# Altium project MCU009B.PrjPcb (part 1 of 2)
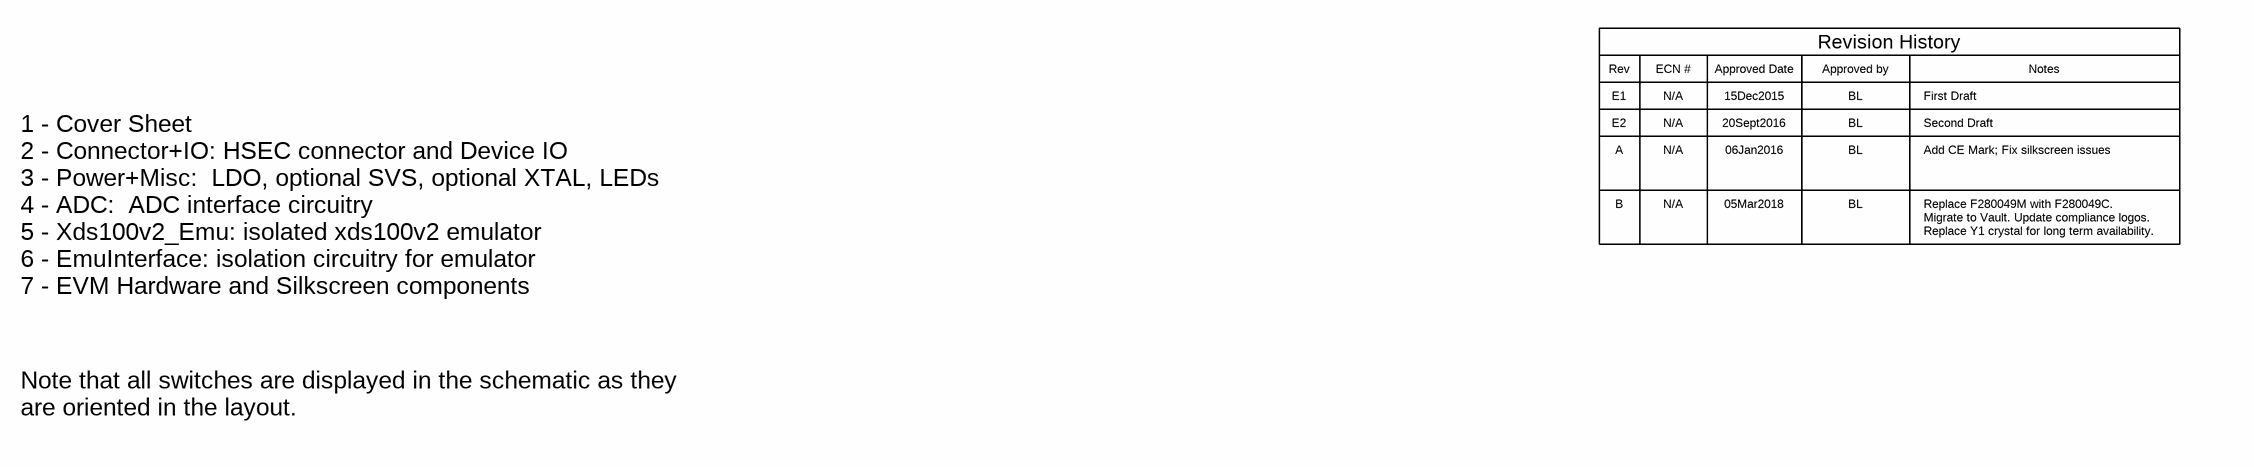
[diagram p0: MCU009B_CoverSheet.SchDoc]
CopyrightYear: 2018; PCB_Layout: QC Graphics; PCB_Rev: B; PRJ_Customer: Public Release; PRJ_Engineer: Brett Larimore; PRJ_Number: MCU009; PRJ_Title: F280049C controlCARD; SCH_Rev: B; TechSupport: http://www.ti.com/support; TID: N/A
7 sheets, 234 parts. Net scope: flat (ports and power ports of the same name join across sheets).
Board file: MCU009B_PCB.PcbDoc
Sheets:
  MCU009B_CoverSheet.SchDoc
  MCU009B_Connector+IO.SchDoc
  MCU009B_Power+Misc.SchDoc
  MCU009B_ADC.SchDoc
  MCU009B_Xds100v2Emu.SchDoc
  MCU009B_EVM_Hardware.SchDoc
  MCU009B_EmuInterface.SchDoc

## Sheet MCU009B_CoverSheet.SchDoc: Cover Sheet
size 431 x 279 mm; Date: Not shown in title block; ApprovedBy: Not shown in title block; CheckedBy: Not shown in title block; Author: Not shown in title block; CompanyName: Not shown in title block; DrawnBy: Brett Larimore; Engineer: Not shown in title block; Organization: Not shown in title block; Address1: Not shown in title block; Address2: Not shown in title block; Address3: Not shown in title block; Address4: Not shown in title block; DocumentNumber: 1; Revision: Use project parameter SCH_Rev; SheetNumber: 1; SheetTotal: 7; PageSetup: Record=PageOptions¦CenterHorizontal=True¦CenterVertical=True¦PrintScale=1.00¦XCorrection=1.00¦YCorrection=1.00¦PrintKind=0¦BorderSize=5000000¦LeftOffset=0¦BottomOffset=0¦Orientation=2¦PaperLength=1000¦PaperWidth=1000¦Scale=100¦PaperSource=15¦PrintQuality=600¦MediaType=1¦DitherType=10¦PaperKind=Letter¦PrintScaleMode=1

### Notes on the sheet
- Rev
- E1
- ECN #
- N/A
- Approved Date
- 15Dec2015
- Approved by
- BL
- Revision History
- First Draft
- Notes
- E2
- A
- 20Sept2016
- 06Jan2016
- Second Draft
- Add CE Mark; Fix silkscreen issues
- B
- 05Mar2018
- Replace F280049M with F280049C.
- Migrate to Vault. Update compliance logos.
- Replace Y1 crystal for long term availability.
- 1 - Cover Sheet
  2 - Connector+IO: HSEC connector and Device IO
  3 - Power+Misc:  LDO, optional SVS, optional XTAL, LEDs
  4 - ADC:  ADC interface circuitry
  5 - Xds100v2_Emu: isolated xds100v2 emulator
  6 - EmuInterface: isolation circuitry for emulator
  7 - EVM Hardware and Silkscreen components
- Note that all switches are displayed in the schematic as they are oriented in the layout.

## Sheet MCU009B_Connector+IO.SchDoc: Connector+IO
size 431 x 279 mm; Date: Not shown in title block; ApprovedBy: Not shown in title block; CheckedBy: Not shown in title block; Author: Not shown in title block; CompanyName: Not shown in title block; Engineer: Not shown in title block; Organization: Not shown in title block; Address1: Not shown in title block; Address2: Not shown in title block; Address3: Not shown in title block; Address4: Not shown in title block; DocumentNumber: 2; Revision: Use project parameter SCH_Rev; SheetNumber: 2; SheetTotal: 7; PageSetup: Record=PageOptions¦CenterHorizontal=True¦CenterVertical=True¦PrintScale=1.00¦XCorrection=1.00¦YCorrection=1.00¦PrintKind=0¦BorderSize=5000000¦LeftOffset=0¦BottomOffset=0¦Orientation=2¦PaperLength=1000¦PaperWidth=1000¦Scale=100¦PaperSource=15¦PrintQuality=600¦MediaType=1¦DitherType=10¦PaperKind=Letter¦PrintScaleMode=1
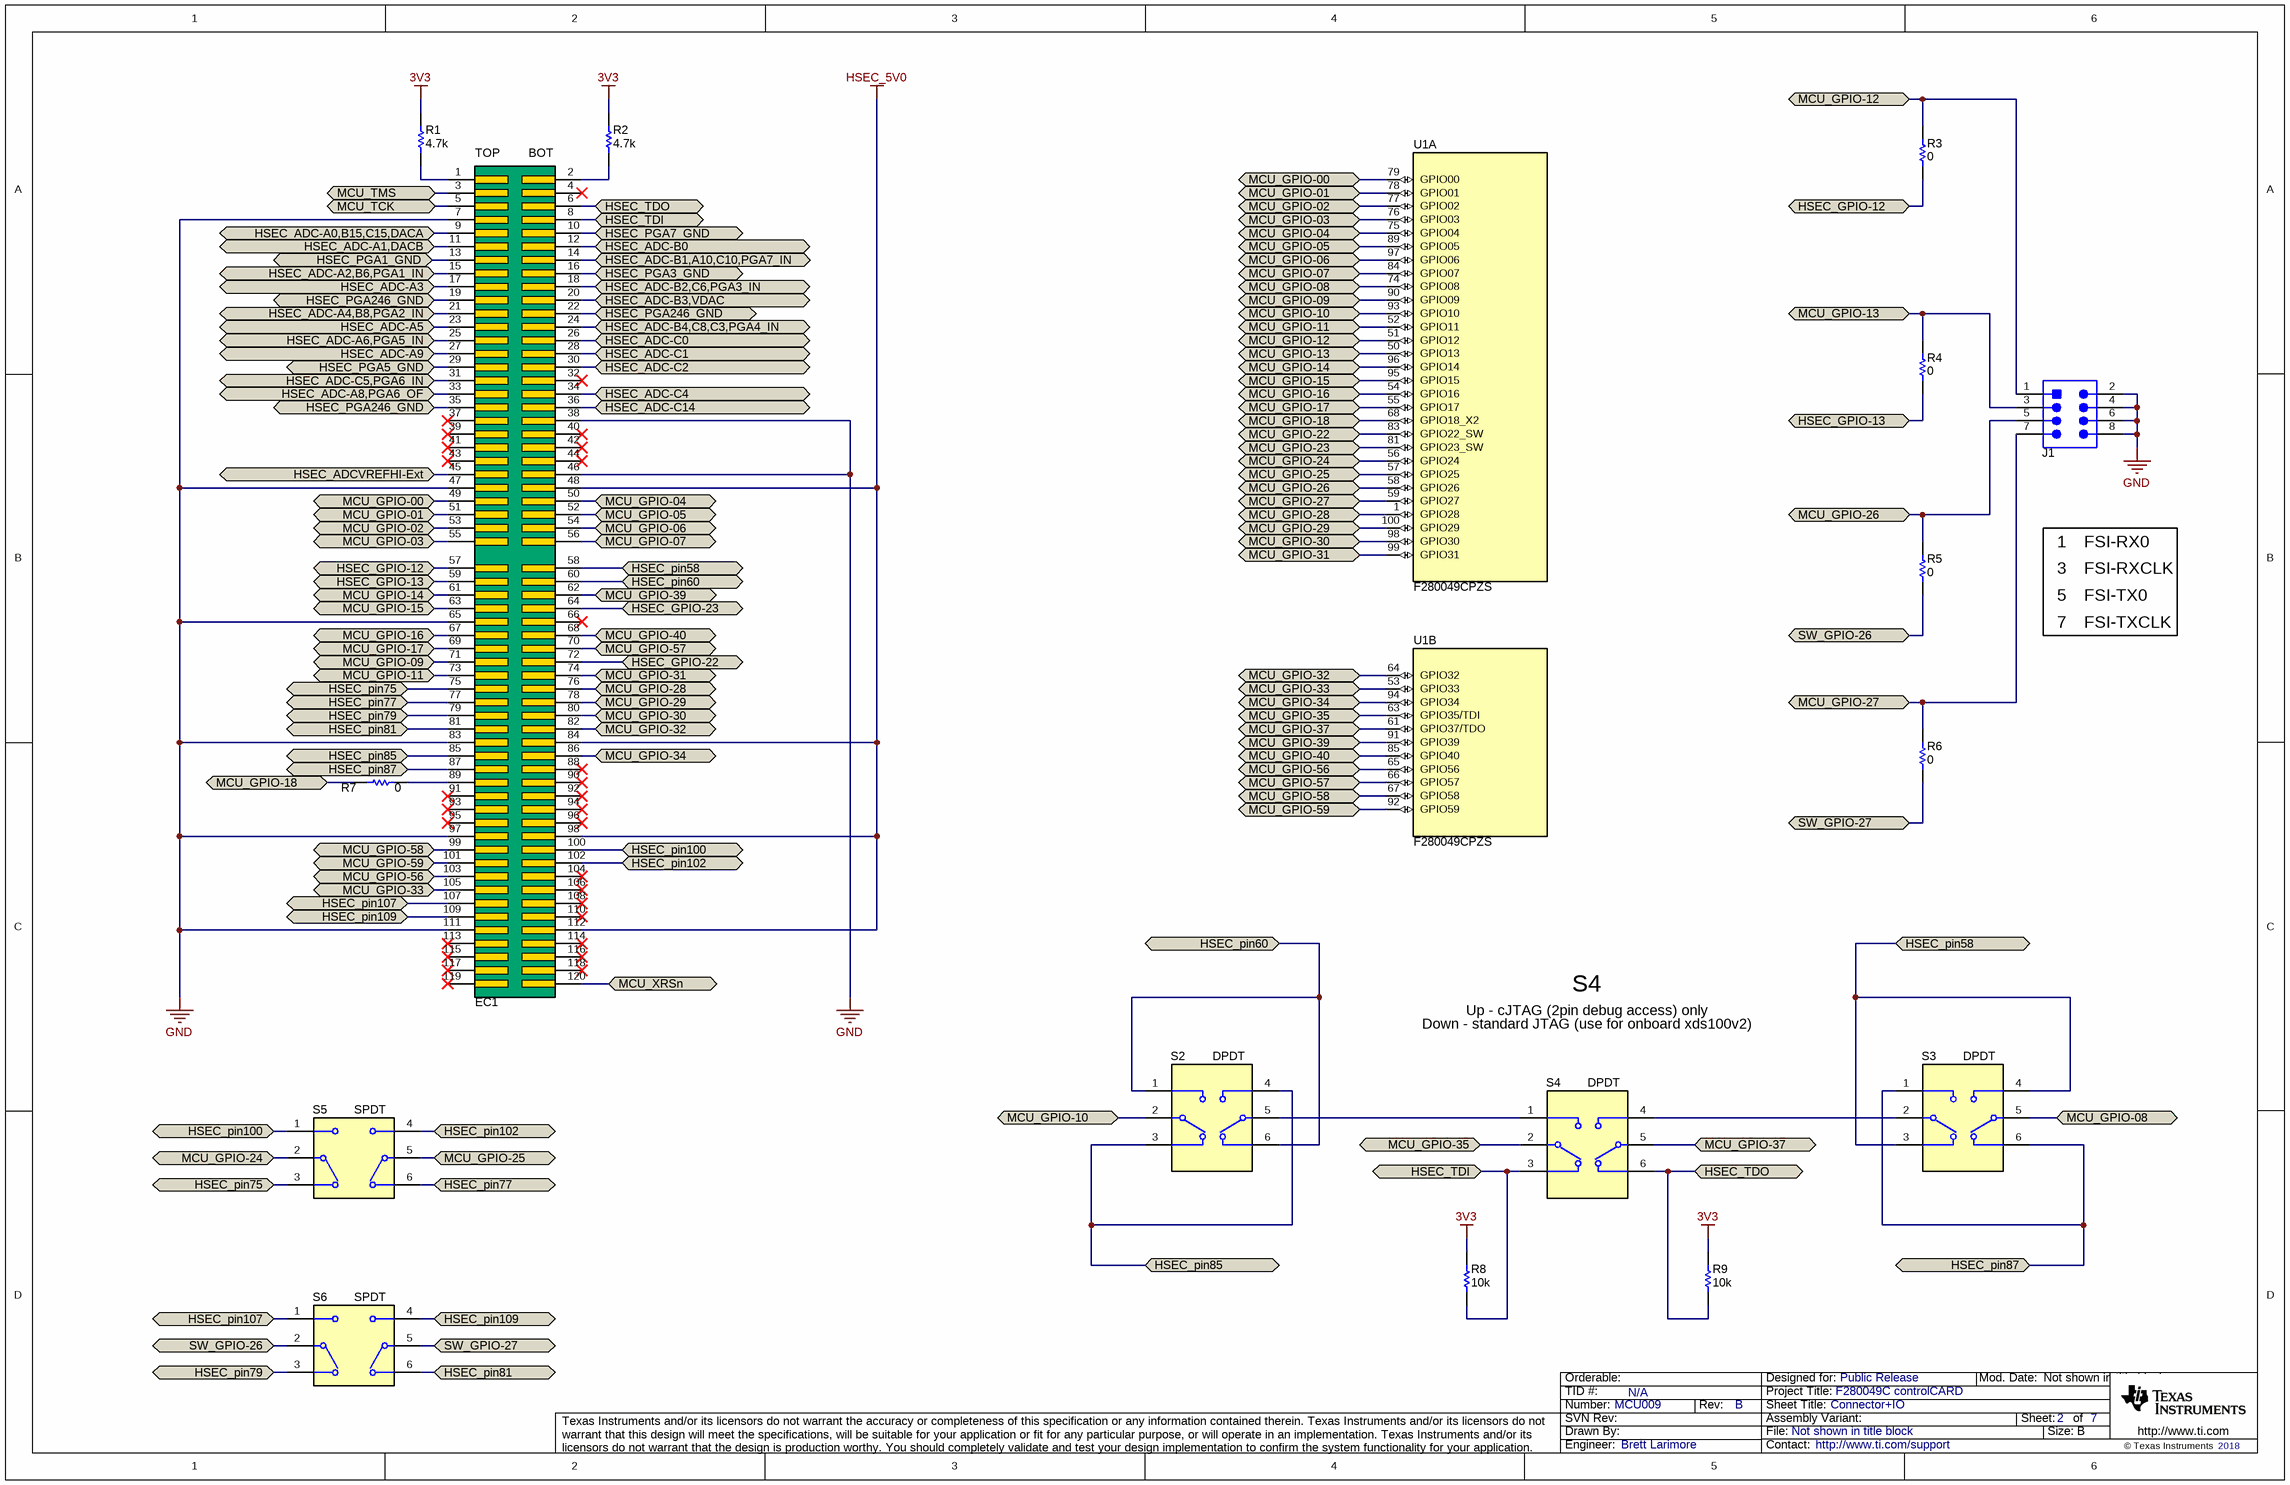
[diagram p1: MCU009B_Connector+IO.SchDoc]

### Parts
(Parts that share a designator on the sheet are numbered #1, #2 ... from top to bottom, then left to right.)
EC1  controlCARD-120HSEC_Edge  [controlCARD-120HSEC_Edge]  (value not drawn)  (no BOM)
J1  TMM-104-01-T-D  [Samtec_TMM-104-01-x-D]  (value not drawn)
R1  ValueDisplayed: 4.7k  [0402]  (hidden comment: CRCW04024K70JNED)
R2  ValueDisplayed: 4.7k  [0402]  (hidden comment: CRCW04024K70JNED)
R3  ValueDisplayed: 0  [0603]  (hidden comment: CRCW06030000Z0EA)
R4  ValueDisplayed: 0  [0603]  (hidden comment: CRCW06030000Z0EA)
R5  ValueDisplayed: 0  [0603]  (hidden comment: CRCW06030000Z0EA)
R6  ValueDisplayed: 0  [0603]  (hidden comment: CRCW06030000Z0EA)
R7  ValueDisplayed: 0  [0603]  (hidden comment: CRCW06030000Z0EA)
R8  ValueDisplayed: 10k  [0402]  (hidden comment: CRCW040210K0JNED)
R9  ValueDisplayed: 10k  [0402]  (hidden comment: CRCW040210K0JNED)
S2  Circuit: DPDT  [SW_CAS-220TA]  (hidden comment: CAS-220TA)
S3  Circuit: DPDT  [SW_CAS-220TA]  (hidden comment: CAS-220TA)
S4  Circuit: DPDT  [SW_CAS-220TA]  (hidden comment: CAS-220TA)
S5  Circuit: SPDT  [SW_CAS-D20TA]  (hidden comment: CAS-D20TA)
S6  Circuit: SPDT  [SW_CAS-D20TA]  (hidden comment: CAS-D20TA)
U1#1  F280049CPZS  [PZ0100A_N]  (parts A,B of 5)

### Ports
HSEC_ADC-A0,B15,C15,DACA (bidir), HSEC_ADC-A1,DACB (bidir), HSEC_ADC-A2,B6,PGA1_IN (bidir), HSEC_ADC-A3 (bidir), HSEC_ADC-A4,B8,PGA2_IN (bidir), HSEC_ADC-A5 (bidir), HSEC_ADC-A6,PGA5_IN (bidir), HSEC_ADC-A8,PGA6_OF (bidir), HSEC_ADC-A9 (bidir), HSEC_ADC-B0 (bidir), HSEC_ADC-B1,A10,C10,PGA7_IN (bidir), HSEC_ADC-B2,C6,PGA3_IN (bidir), HSEC_ADC-B3,VDAC (bidir), HSEC_ADC-B4,C8,C3,PGA4_IN (bidir), HSEC_ADC-C0 (bidir), HSEC_ADC-C1 (bidir), HSEC_ADC-C2 (bidir), HSEC_ADC-C4 (bidir), HSEC_ADC-C5,PGA6_IN (bidir), HSEC_ADC-C14 (bidir), HSEC_ADCVREFHI-Ext (bidir), HSEC_GPIO-12 (bidir), HSEC_GPIO-13 (bidir), HSEC_GPIO-22 (bidir), HSEC_GPIO-23 (bidir), HSEC_PGA1_GND (bidir), HSEC_PGA3_GND (bidir), HSEC_PGA5_GND (bidir), HSEC_PGA7_GND (bidir), HSEC_PGA246_GND (bidir), HSEC_pin58 (bidir), HSEC_pin60 (bidir), HSEC_pin75 (bidir), HSEC_pin77 (bidir), HSEC_pin79 (bidir), HSEC_pin81 (bidir), HSEC_pin85 (bidir), HSEC_pin87 (bidir), HSEC_pin100 (bidir), HSEC_pin102 (bidir), HSEC_pin107 (bidir), HSEC_pin109 (bidir), HSEC_TDI (bidir), HSEC_TDO (bidir), MCU_GPIO-00 (bidir), MCU_GPIO-01 (bidir), MCU_GPIO-02 (bidir), MCU_GPIO-03 (bidir), MCU_GPIO-04 (bidir), MCU_GPIO-05 (bidir), MCU_GPIO-06 (bidir), MCU_GPIO-07 (bidir), MCU_GPIO-08 (bidir), MCU_GPIO-09 (bidir), MCU_GPIO-10 (bidir), MCU_GPIO-11 (bidir), MCU_GPIO-12 (bidir), MCU_GPIO-13 (bidir), MCU_GPIO-14 (bidir), MCU_GPIO-15 (bidir), MCU_GPIO-16 (bidir), MCU_GPIO-17 (bidir), MCU_GPIO-18 (bidir), MCU_GPIO-22 (bidir), MCU_GPIO-23 (bidir), MCU_GPIO-24 (bidir), MCU_GPIO-25 (bidir), MCU_GPIO-26 (bidir), MCU_GPIO-27 (bidir), MCU_GPIO-28 (bidir), MCU_GPIO-29 (bidir), MCU_GPIO-30 (bidir), MCU_GPIO-31 (bidir), MCU_GPIO-32 (bidir), MCU_GPIO-33 (bidir), MCU_GPIO-34 (bidir), MCU_GPIO-35 (bidir), MCU_GPIO-37 (bidir), MCU_GPIO-39 (bidir), MCU_GPIO-40 (bidir), MCU_GPIO-56 (bidir), MCU_GPIO-57 (bidir), MCU_GPIO-58 (bidir), MCU_GPIO-59 (bidir), MCU_TCK (bidir), MCU_TMS (bidir), MCU_XRSn (bidir), SW_GPIO-26 (bidir), SW_GPIO-27 (bidir)

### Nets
3V3: R1.1 R2.2 R8.2 R9.2
GND: EC1.7 EC1.38 EC1.46 EC1.47 EC1.65 EC1.83 EC1.97 EC1.111 J1.2 J1.4 J1.6 J1.8
HSEC_5V0: EC1.48 EC1.84 EC1.98 EC1.112
HSEC_ADC-A0,B15,C15,DACA: EC1.9 ; port HSEC_ADC-A0,B15,C15,DACA
HSEC_ADC-A1,DACB: EC1.11 ; port HSEC_ADC-A1,DACB
HSEC_ADC-A2,B6,PGA1_IN: EC1.15 ; port HSEC_ADC-A2,B6,PGA1_IN
HSEC_ADC-A3: EC1.17 ; port HSEC_ADC-A3
HSEC_ADC-A4,B8,PGA2_IN: EC1.21 ; port HSEC_ADC-A4,B8,PGA2_IN
HSEC_ADC-A5: EC1.23 ; port HSEC_ADC-A5
HSEC_ADC-A6,PGA5_IN: EC1.25 ; port HSEC_ADC-A6,PGA5_IN
HSEC_ADC-A8,PGA6_OF: EC1.33 ; port HSEC_ADC-A8,PGA6_OF
HSEC_ADC-A9: EC1.27 ; port HSEC_ADC-A9
HSEC_ADC-B0: EC1.12 ; port HSEC_ADC-B0
HSEC_ADC-B1,A10,C10,PGA7_IN: EC1.14 ; port HSEC_ADC-B1,A10,C10,PGA7_IN
HSEC_ADC-B2,C6,PGA3_IN: EC1.18 ; port HSEC_ADC-B2,C6,PGA3_IN
HSEC_ADC-B3,VDAC: EC1.20 ; port HSEC_ADC-B3,VDAC
HSEC_ADC-B4,C8,C3,PGA4_IN: EC1.24 ; port HSEC_ADC-B4,C8,C3,PGA4_IN
HSEC_ADC-C0: EC1.26 ; port HSEC_ADC-C0
HSEC_ADC-C1: EC1.28 ; port HSEC_ADC-C1
HSEC_ADC-C2: EC1.30 ; port HSEC_ADC-C2
HSEC_ADC-C4: EC1.34 ; port HSEC_ADC-C4
HSEC_ADC-C5,PGA6_IN: EC1.31 ; port HSEC_ADC-C5,PGA6_IN
HSEC_ADC-C14: EC1.36 ; port HSEC_ADC-C14
HSEC_ADCVREFHI-Ext: EC1.45 ; port HSEC_ADCVREFHI-Ext
HSEC_GPIO-12: EC1.57 R3.1 ; port HSEC_GPIO-12
HSEC_GPIO-13: EC1.59 R4.1 ; port HSEC_GPIO-13
HSEC_GPIO-22: EC1.72 ; port HSEC_GPIO-22
HSEC_GPIO-23: EC1.64 ; port HSEC_GPIO-23
HSEC_PGA1_GND: EC1.13 ; port HSEC_PGA1_GND
HSEC_PGA3_GND: EC1.16 ; port HSEC_PGA3_GND
HSEC_PGA5_GND: EC1.29 ; port HSEC_PGA5_GND
HSEC_PGA7_GND: EC1.10 ; port HSEC_PGA7_GND
HSEC_PGA246_GND: EC1.19 EC1.22 EC1.35 ; port HSEC_PGA246_GND
HSEC_pin58: EC1.58 S3.3 S3.4 ; port HSEC_pin58
HSEC_pin60: EC1.60 S2.1 S2.6 ; port HSEC_pin60
HSEC_pin75: EC1.75 S5.3 ; port HSEC_pin75
HSEC_pin77: EC1.77 S5.6 ; port HSEC_pin77
HSEC_pin79: EC1.79 S6.3 ; port HSEC_pin79
HSEC_pin81: EC1.81 S6.6 ; port HSEC_pin81
HSEC_pin85: EC1.85 S2.3 S2.4 ; port HSEC_pin85
HSEC_pin87: EC1.87 S3.1 S3.6 ; port HSEC_pin87
HSEC_pin100: EC1.100 S5.1 ; port HSEC_pin100
HSEC_pin102: EC1.102 S5.4 ; port HSEC_pin102
HSEC_pin107: EC1.107 S6.1 ; port HSEC_pin107
HSEC_pin109: EC1.109 S6.4 ; port HSEC_pin109
HSEC_TDI: EC1.8 R8.1 S4.3 ; port HSEC_TDI
HSEC_TDO: EC1.6 R9.1 S4.6 ; port HSEC_TDO
MCU_GPIO-00: EC1.49 U1#1.79(GPIO00) ; port MCU_GPIO-00
MCU_GPIO-01: EC1.51 U1#1.78(GPIO01) ; port MCU_GPIO-01
MCU_GPIO-02: EC1.53 U1#1.77(GPIO02) ; port MCU_GPIO-02
MCU_GPIO-03: EC1.55 U1#1.76(GPIO03) ; port MCU_GPIO-03
MCU_GPIO-04: EC1.50 U1#1.75(GPIO04) ; port MCU_GPIO-04
MCU_GPIO-05: EC1.52 U1#1.89(GPIO05) ; port MCU_GPIO-05
MCU_GPIO-06: EC1.54 U1#1.97(GPIO06) ; port MCU_GPIO-06
MCU_GPIO-07: EC1.56 U1#1.84(GPIO07) ; port MCU_GPIO-07
MCU_GPIO-08: S3.5 U1#1.74(GPIO08) ; port MCU_GPIO-08
MCU_GPIO-09: EC1.71 U1#1.90(GPIO09) ; port MCU_GPIO-09
MCU_GPIO-10: S2.2 U1#1.93(GPIO10) ; port MCU_GPIO-10
MCU_GPIO-11: EC1.73 U1#1.52(GPIO11) ; port MCU_GPIO-11
MCU_GPIO-12: J1.1 R3.2 U1#1.51(GPIO12) ; port MCU_GPIO-12
MCU_GPIO-13: J1.3 R4.2 U1#1.50(GPIO13) ; port MCU_GPIO-13
MCU_GPIO-14: EC1.61 U1#1.96(GPIO14) ; port MCU_GPIO-14
MCU_GPIO-15: EC1.63 U1#1.95(GPIO15) ; port MCU_GPIO-15
MCU_GPIO-16: EC1.67 U1#1.54(GPIO16) ; port MCU_GPIO-16
MCU_GPIO-17: EC1.69 U1#1.55(GPIO17) ; port MCU_GPIO-17
MCU_GPIO-18: R7.2 U1#1.68(GPIO18_X2) ; port MCU_GPIO-18
MCU_GPIO-22: U1#1.83(GPIO22_SW) ; port MCU_GPIO-22
MCU_GPIO-23: U1#1.81(GPIO23_SW) ; port MCU_GPIO-23
MCU_GPIO-24: S5.2(C) U1#1.56(GPIO24) ; port MCU_GPIO-24
MCU_GPIO-25: S5.5(C) U1#1.57(GPIO25) ; port MCU_GPIO-25
MCU_GPIO-26: J1.5 R5.2 U1#1.58(GPIO26) ; port MCU_GPIO-26
MCU_GPIO-27: J1.7 R6.2 U1#1.59(GPIO27) ; port MCU_GPIO-27
MCU_GPIO-28: EC1.76 U1#1.1(GPIO28) ; port MCU_GPIO-28
MCU_GPIO-29: EC1.78 U1#1.100(GPIO29) ; port MCU_GPIO-29
MCU_GPIO-30: EC1.80 U1#1.98(GPIO30) ; port MCU_GPIO-30
MCU_GPIO-31: EC1.74 U1#1.99(GPIO31) ; port MCU_GPIO-31
MCU_GPIO-32: EC1.82 U1#1.64(GPIO32) ; port MCU_GPIO-32
MCU_GPIO-33: EC1.105 U1#1.53(GPIO33) ; port MCU_GPIO-33
MCU_GPIO-34: EC1.86 U1#1.94(GPIO34) ; port MCU_GPIO-34
MCU_GPIO-35: S4.2 U1#1.63(GPIO35/TDI) ; port MCU_GPIO-35
MCU_GPIO-37: S4.5 U1#1.61(GPIO37/TDO) ; port MCU_GPIO-37
MCU_GPIO-39: EC1.62 U1#1.91(GPIO39) ; port MCU_GPIO-39
MCU_GPIO-40: EC1.68 U1#1.85(GPIO40) ; port MCU_GPIO-40
MCU_GPIO-56: EC1.103 U1#1.65(GPIO56) ; port MCU_GPIO-56
MCU_GPIO-57: EC1.70 U1#1.66(GPIO57) ; port MCU_GPIO-57
MCU_GPIO-58: EC1.99 U1#1.67(GPIO58) ; port MCU_GPIO-58
MCU_GPIO-59: EC1.101 U1#1.92(GPIO59) ; port MCU_GPIO-59
MCU_TCK: EC1.5 ; port MCU_TCK
MCU_TMS: EC1.3 ; port MCU_TMS
MCU_XRSn: EC1.120 ; port MCU_XRSn
SW_GPIO-26: R5.1 S6.2(C) ; port SW_GPIO-26
SW_GPIO-27: R6.1 S6.5(C) ; port SW_GPIO-27
NetEC1_1: EC1.1 R1.2
NetEC1_2: EC1.2 R2.1
NetEC1_89: EC1.89 R7.1
NetS2_5: S2.5 S4.1
NetS3_2: S3.2 S4.4

Not connected (* = marked no-connect by the designer): EC1 4* 32* 37* 39* 40* 41* 42* 43* 44* 66* 88* 90* 91* 92* 93* 94* 95* 96* 104* 106* 108* 110* 113* 114* 115* 116* 117* 118* 119*

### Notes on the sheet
- 1
- 3
- FSI-RX0
- FSI-RXCLK
- 5
- 7
- FSI-TX0
- FSI-TXCLK
- S4
- Up - cJTAG (2pin debug access) only
- Down - standard JTAG (use for onboard xds100v2)

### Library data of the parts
EC1 = CMP-0003813-2: C2000 controlCARD-120HSEC Edge Connector for Samtec HSEC8-160-01-L-DV-A-BL; Manufacturer: Any; Note: The pin numbering does not match Samtec datasheet
J1 = CMP-0055568-1: Header, 2mm, 4x2, Tin, TH; Manufacturer: Samtec; Pitch_mm: 2; Gender: Male; Shrouded: N; Current_A: 3.2A; Cert_CSA: Y; CNHeader: TRUE; CT: FALSE
R1 R2 = CMP-0026938-5: RES, 4.7 k, 5%, 0.063 W, AEC-Q200 Grade 0, 0402; Manufacturer: Vishay-Dale; Value: 4.7k; Value_Code: 4k70; Power_W: 63mW; Value2: 0.063W; VDC_V: 50V; TempCo: 200 ppm/C; EIA_Code: E24; AEC Category: Q200; AEC Qualified: Y; AEC Grade: 0; SizeArea_mm2: 0.5; SizeX_mm: 1; SizeZ_mm: 0.6
R3-R7 = CMP-0025697-4: RES, 0, 5%, 0.1 W, AEC-Q200 Grade 0, 0603; Manufacturer: Vishay-Dale; Value: 0; Value_Code: 0000; Power_W: 100mW; Value2: 0.1W; VDC_V: 75V; TempCo: 200 ppm/C; EIA_Code: E24; AEC Category: Q200; AEC Qualified: Y; SizeArea_mm2: 1.28; SizeX_mm: 1.6; SizeY_mm: 0.8; SizeZ_mm: 1
R8 R9 = CMP-0026825-5: RES, 10 k, 5%, 0.063 W, AEC-Q200 Grade 0, 0402; Manufacturer: Vishay-Dale; Value: 10k; Value_Code: 10k0; Power_W: 63mW; Value2: 0.063W; VDC_V: 50V; TempCo: 200 ppm/C; EIA_Code: E24; AEC Category: Q200; AEC Qualified: Y; AEC Grade: 0; SizeArea_mm2: 0.5; SizeX_mm: 1; SizeZ_mm: 0.6
S2-S4 = CMP-0002123-2: SLIDE SWITCH DPDT  .1A, SMT; Manufacturer: Copal Electronics; VDC_V: 6V; SwitchFunction: On-On; PositionCount: 2; CurrentRating_mA: 100A
S5 S6 = CMP-0002233-1: Switch, Dual SPDT,  2 Pos, 0.1A, 6VDC, SMD; Manufacturer: Copal Electronics; VDC_V: 6V; SwitchFunction: On-On; PositionCount: 2; CurrentRating_mA: 100A
U1#1 = CMP-0078352-1: Piccolo Microcontroller, PZ0100A (LQFP-100); Manufacturer: Texas Instruments; SizeArea_mm2: 256; SizeAreaWB_mm2: 324; SizeX_mm: 16; SizeZ_mm: 1.6; CompType: IC; AEC Category: Q200; AEC Qualified: N

## Sheet MCU009B_Power+Misc.SchDoc: Power+Misc
size 431 x 279 mm; Date: Not shown in title block; ApprovedBy: Not shown in title block; CheckedBy: Not shown in title block; Author: Not shown in title block; CompanyName: Not shown in title block; Engineer: Not shown in title block; Organization: Not shown in title block; Address1: Not shown in title block; Address2: Not shown in title block; Address3: Not shown in title block; Address4: Not shown in title block; DocumentNumber: 3; Revision: Use project parameter SCH_Rev; SheetNumber: 3; SheetTotal: 7; PageSetup: Record=PageOptions¦CenterHorizontal=True¦CenterVertical=True¦PrintScale=0.64¦XCorrection=1.00¦YCorrection=1.00¦PrintKind=0¦BorderSize=5000000¦LeftOffset=0¦BottomOffset=0¦Orientation=2¦PaperLength=1000¦PaperWidth=1000¦Scale=100¦PaperSource=15¦PrintQuality=600¦MediaType=1¦DitherType=10¦PrintScaleMode=1¦PaperKind=Letter
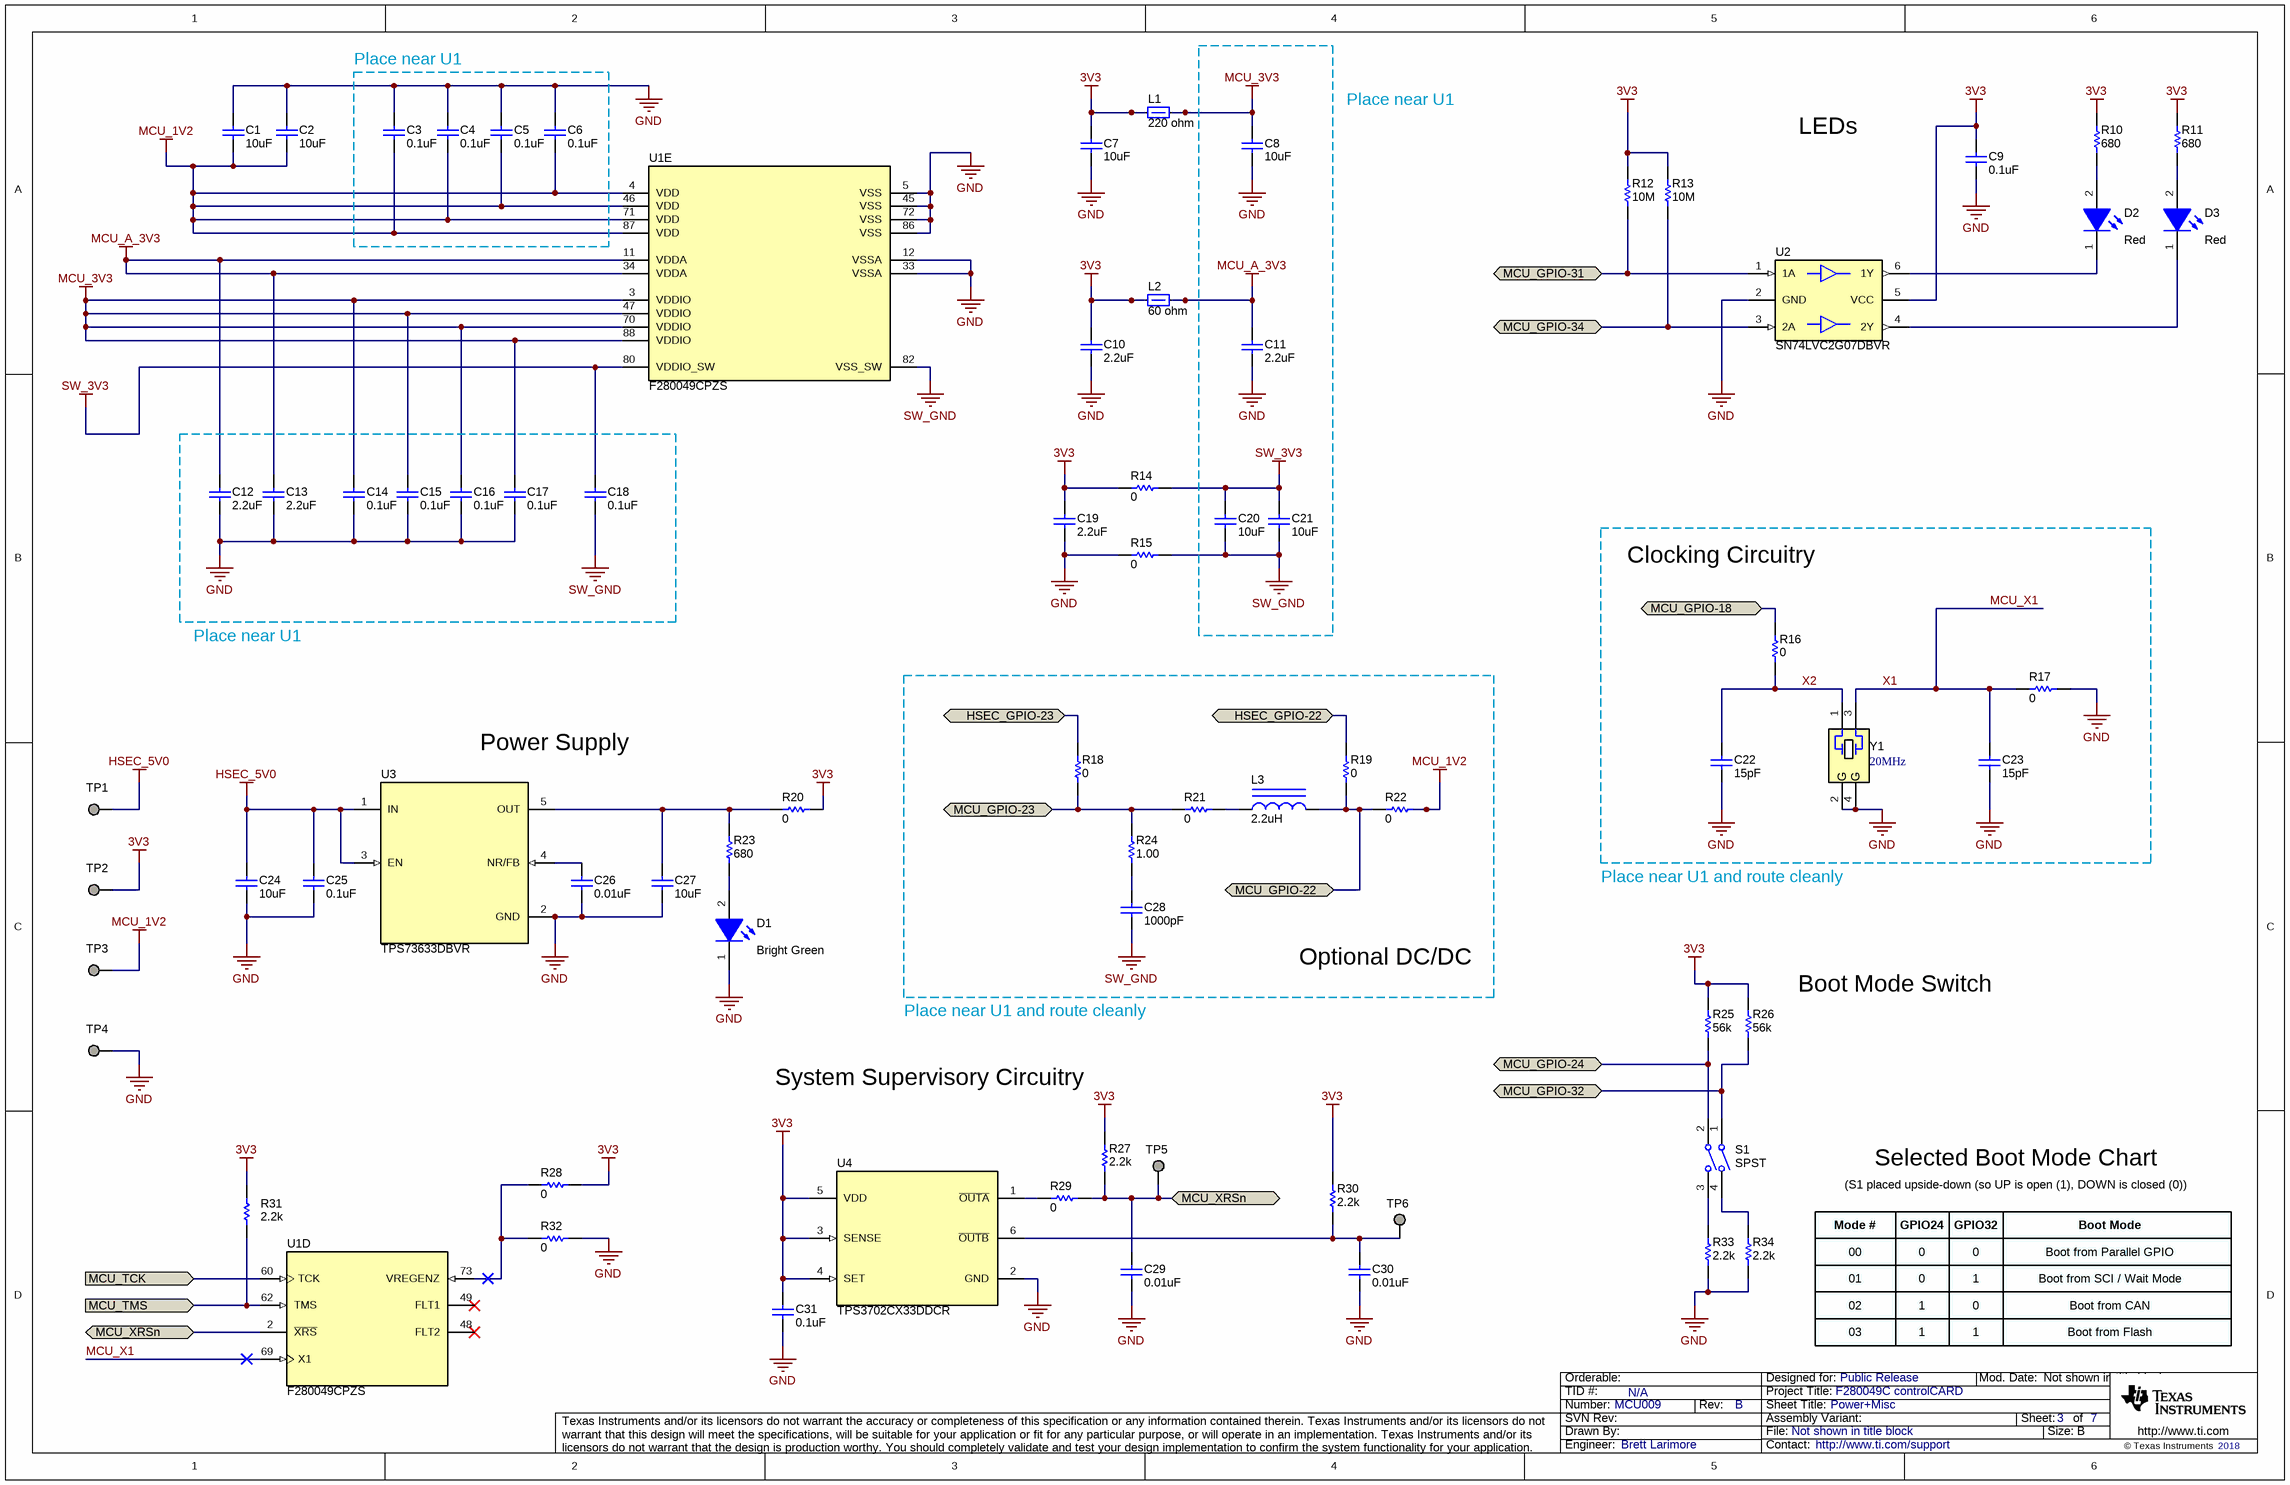
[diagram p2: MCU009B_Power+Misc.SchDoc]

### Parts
(Parts that share a designator on the sheet are numbered #1, #2 ... from top to bottom, then left to right.)
C1  ValueDisplayed: 10uF  [0603]  (hidden comment: GRM188R61A106ME69D)
C2  ValueDisplayed: 10uF  [0603]  (hidden comment: GRM188R61A106ME69D)
C3  ValueDisplayed: 0.1uF  [0402]  (hidden comment: GRM155R71A104KA01D)
C4  ValueDisplayed: 0.1uF  [0402]  (hidden comment: GRM155R71A104KA01D)
C5  ValueDisplayed: 0.1uF  [0402]  (hidden comment: GRM155R71A104KA01D)
C6  ValueDisplayed: 0.1uF  [0402]  (hidden comment: GRM155R71A104KA01D)
C7  ValueDisplayed: 10uF  [0805_HV]  (hidden comment: GRM21BR61A106KE19L)
C8  ValueDisplayed: 10uF  [0603]  (hidden comment: GRM188R61A106ME69D)
C9  ValueDisplayed: 0.1uF  [0402]  (hidden comment: GRM155R71A104KA01D)
C10  ValueDisplayed: 2.2uF  [0603]  (hidden comment: GRM188R61A225KE34D)
C11  ValueDisplayed: 2.2uF  [0603]  (hidden comment: GRM188R61A225KE34D)
C12  ValueDisplayed: 2.2uF  [0603]  (hidden comment: GRM188R61A225KE34D)
C13  ValueDisplayed: 2.2uF  [0603]  (hidden comment: GRM188R61A225KE34D)
C14  ValueDisplayed: 0.1uF  [0402]  (hidden comment: GRM155R71A104KA01D)
C15  ValueDisplayed: 0.1uF  [0402]  (hidden comment: GRM155R71A104KA01D)
C16  ValueDisplayed: 0.1uF  [0402]  (hidden comment: GRM155R71A104KA01D)
C17  ValueDisplayed: 0.1uF  [0402]  (hidden comment: GRM155R71A104KA01D)
C18  ValueDisplayed: 0.1uF  [0402]  (hidden comment: GRM155R71A104KA01D)
C19  ValueDisplayed: 2.2uF  [0603]  (hidden comment: GRM188R61A225KE34D)
C20  ValueDisplayed: 10uF  [0603]  (hidden comment: GRM188R61A106ME69D)
C21  ValueDisplayed: 10uF  [0603]  (hidden comment: GRM188R61A106ME69D)
C22  ValueDisplayed: 15pF  [0402]  (hidden comment: GRM1555C1H150JA01D)
C23  ValueDisplayed: 15pF  [0402]  (hidden comment: GRM1555C1H150JA01D)
C24  ValueDisplayed: 10uF  [0603]  (hidden comment: GRM188R61A106ME69D)
C25  ValueDisplayed: 0.1uF  [0402]  (hidden comment: GRM155R71A104KA01D)
C26  ValueDisplayed: 0.01uF  [0402]  (hidden comment: GRM155R71C103KA01D)
C27  ValueDisplayed: 10uF  [0603]  (hidden comment: GRM188R61A106ME69D)
C28  ValueDisplayed: 1000pF  [0402]  (hidden comment: GRM155R71C102KA01D)
C29  ValueDisplayed: 0.01uF  [0402]  (hidden comment: GRM155R71C103KA01D)
C30  ValueDisplayed: 0.01uF  [0402]  (hidden comment: GRM155R71C103KA01D)
C31  ValueDisplayed: 0.1uF  [0402]  (hidden comment: GRM155R71A104KA01D)
D1  value Bright Green  [WL-SMCW_Green_0805]  (hidden comment: 150080VS75000)
D2  value Red  [WL-SMCW_RED_0805]  (hidden comment: 150080SS75000)
D3  value Red  [WL-SMCW_RED_0805]  (hidden comment: 150080SS75000)
L1  value 220 ohm  [0805_HV]  (hidden comment: BLM21PG221SN1D)
L2  value 60 ohm  [0805_HV]  (hidden comment: BKP2125HS600-T)
L3  ValueDisplayed: 2.2uH  [1008]  (hidden comment: LQM2HPN2R2MG0L)
R10  ValueDisplayed: 680  [0402]  (hidden comment: CRCW0402680RJNED)
R11  ValueDisplayed: 680  [0402]  (hidden comment: CRCW0402680RJNED)
R12  ValueDisplayed: 10M  [0402]  (hidden comment: CRCW040210M0JNED)
R13  ValueDisplayed: 10M  [0402]  (hidden comment: CRCW040210M0JNED)
R14  ValueDisplayed: 0  [0805_HV]  (hidden comment: CRCW08050000Z0EA)
R15  ValueDisplayed: 0  [0805_HV]  (hidden comment: CRCW08050000Z0EA)
R16  ValueDisplayed: 0  [0603]  (hidden comment: CRCW06030000Z0EA)
R17  ValueDisplayed: 0  [0603]  (hidden comment: CRCW06030000Z0EA)
R18  ValueDisplayed: 0  [0603]  (hidden comment: CRCW06030000Z0EA)
R19  ValueDisplayed: 0  [0603]  (hidden comment: CRCW06030000Z0EA)
R20  ValueDisplayed: 0  [0805_HV]  (hidden comment: CRCW08050000Z0EA)
R21  ValueDisplayed: 0  [0603]  (hidden comment: CRCW06030000Z0EA)
R22  ValueDisplayed: 0  [0603]  (hidden comment: CRCW06030000Z0EA)
R23  ValueDisplayed: 680  [0402]  (hidden comment: CRCW0402680RJNED)
R24  ValueDisplayed: 1.00  [0402]  (hidden comment: CRCW04021R00FKED)
R25  ValueDisplayed: 56k  [0402]  (hidden comment: CRCW040256K0JNED)
R26  ValueDisplayed: 56k  [0402]  (hidden comment: CRCW040256K0JNED)
R27  ValueDisplayed: 2.2k  [0402]  (hidden comment: CRCW04022K20JNED)
R28  ValueDisplayed: 0  [0603]  (hidden comment: CRCW06030000Z0EA)
R29  ValueDisplayed: 0  [0402]  (hidden comment: CRCW04020000Z0ED)
R30  ValueDisplayed: 2.2k  [0402]  (hidden comment: CRCW04022K20JNED)
R31  ValueDisplayed: 2.2k  [0402]  (hidden comment: CRCW04022K20JNED)
R32  ValueDisplayed: 0  [0603]  (hidden comment: CRCW06030000Z0EA)
R33  ValueDisplayed: 2.2k  [0402]  (hidden comment: CRCW04022K20JNED)
R34  ValueDisplayed: 2.2k  [0402]  (hidden comment: CRCW04022K20JNED)
S1  Circuit: SPST  [SW_218-2LP]  (hidden comment: 218-2LPST)
TP1  TESTPOINT  [TP_50MIL-25MILHOLE]  (value not drawn)  (no BOM)
TP2  TESTPOINT  [TP_50MIL-25MILHOLE]  (value not drawn)  (no BOM)
TP3  TESTPOINT  [TP_50MIL-25MILHOLE]  (value not drawn)  (no BOM)
TP4  TESTPOINT  [TP_50MIL-25MILHOLE]  (value not drawn)  (no BOM)
TP5  TESTPOINT  [TP_50MIL-25MILHOLE]  (value not drawn)  (no BOM)
TP6  TESTPOINT  [TP_50MIL-25MILHOLE]  (value not drawn)  (no BOM)
U1#1  F280049CPZS  [PZ0100A_N]  (parts D,E of 5)
U2  SN74LVC2G07DBVR  [DBV0006A_N]
U3  TPS73633DBVR  [DBV0005A_N]
U4  TPS3702CX33DDCR  [DDC0006A_N]
Y1  20MHz  [ECS_ECX-53B]

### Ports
HSEC_GPIO-22 (bidir), HSEC_GPIO-23 (bidir), MCU_GPIO-18 (bidir), MCU_GPIO-22 (bidir), MCU_GPIO-23 (bidir), MCU_GPIO-24 (bidir), MCU_GPIO-31 (bidir), MCU_GPIO-32 (bidir), MCU_GPIO-34 (bidir), MCU_TCK (in), MCU_TMS (in), MCU_XRSn (bidir)

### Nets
3V3: C7.2 C9.1 C10.2 C19.2 C31.1 L1.1 L2.1 R10.1 R11.1 R12.2 R13.2 R14.1 R20.2 R25.1 R26.2 R27.2 R28.2 R30.2 R31.2 TP2.1 U2.5(VCC) U4.3(SENSE) U4.4(SET) U4.5(VDD)
GND: C1.2 C2.2 C3.1 C4.1 C5.1 C6.1 C7.1 C8.2 C9.2 C10.1 C11.1 C12.1 C13.1 C14.2 C15.2 C16.2 C17.2 C19.1 C22.2 C23.2 C24.2 C25.2 C26.1 C27.1 C29.1 C30.1 C31.2 D1.1(K) R15.1 R17.1 R32.2 R33.2 R34.1 TP4.1 U1#1.5(VSS) U1#1.12(VSSA) U1#1.33(VSSA) U1#1.45(VSS) U1#1.72(VSS) U1#1.86(VSS) U2.2(GND) U3.2(GND) U4.2(GND) Y1.2(GND) Y1.4(GND)
HSEC_5V0: C24.1 C25.1 TP1.1 U3.1(IN) U3.3(EN)
MCU_1V2: C1.1 C2.1 C3.2 C4.2 C5.2 C6.2 R22.1 TP3.1 U1#1.4(VDD) U1#1.46(VDD) U1#1.71(VDD) U1#1.87(VDD)
MCU_3V3: C8.1 C14.1 C15.1 C16.1 C17.1 L1.2 U1#1.3(VDDIO) U1#1.47(VDDIO) U1#1.70(VDDIO) U1#1.88(VDDIO)
MCU_A_3V3: C11.2 C12.2 C13.2 L2.2 U1#1.11(VDDA) U1#1.34(VDDA)
SW_3V3: C18.1 C20.2 C21.2 R14.2 U1#1.80(VDDIO_SW)
SW_GND: C18.2 C20.1 C21.1 C28.2 R15.2 U1#1.82(VSS_SW)
HSEC_GPIO-22: R19.2 ; port HSEC_GPIO-22
HSEC_GPIO-23: R18.2 ; port HSEC_GPIO-23
MCU_GPIO-18: R16.2 ; port MCU_GPIO-18
MCU_GPIO-22: L3.2 R19.1 R22.2 ; port MCU_GPIO-22
MCU_GPIO-23: R18.1 R21.2 R24.2 ; port MCU_GPIO-23
MCU_GPIO-24: R25.2 S1.2 ; port MCU_GPIO-24
MCU_GPIO-31: R12.1 U2.1(1A) ; port MCU_GPIO-31
MCU_GPIO-32: R26.1 S1.1 ; port MCU_GPIO-32
MCU_GPIO-34: R13.1 U2.3(2A) ; port MCU_GPIO-34
MCU_TCK: U1#1.60(TCK) ; port MCU_TCK
MCU_TMS: R31.1 U1#1.62(TMS) ; port MCU_TMS
MCU_X1: C23.1 R17.2 U1#1.69(X1) Y1.3  [also labelled X1]
MCU_XRSn: C29.2 R27.1 R29.2 TP5.1 U1#1.2(~{XRS}) ; port MCU_XRSn
X2: C22.1 R16.1 Y1.1
NetC26_2: C26.2 U3.4(NR/FB)
NetC27_2: C27.2 R20.1 R23.1 U3.5(OUT)
NetC28_1: C28.1 R24.1
NetC30_2: C30.2 R30.1 TP6.1 U4.6(~{OUTB})
NetD1_2: D1.2(A) R23.2
NetD2_1: D2.1(K) U2.6(1Y)
NetD2_2: D2.2(A) R10.2
NetD3_1: D3.1(K) U2.4(2Y)
NetD3_2: D3.2(A) R11.2
NetL3_1: L3.1 R21.1
NetR28_1: R28.1 R32.1 U1#1.73(VREGENZ)
NetR29_1: R29.1 U4.1(~{OUTA})
NetR33_1: R33.1 S1.3
NetR34_2: R34.2 S1.4

Not connected (* = marked no-connect by the designer): U1#1 48(FLT2)* 49(FLT1)*

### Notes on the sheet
- Place near U1
- LEDs
- Clocking Circuitry
- Power Supply
- Place near U1 and route cleanly
- Optional DC/DC
- (near R26) Boot Mode Switch
- System Supervisory Circuitry
- Selected Boot Mode Chart
- Mode #
- GPIO24
- GPIO32
- (S1 placed upside-down (so UP is open (1), DOWN is closed (0))
- Boot Mode
- 00
- 01
- 02
- 0
- 1
- Boot from Parallel GPIO
- Boot from SCI / Wait Mode
- Boot from CAN
- 03
- Boot from Flash

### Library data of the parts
C1 C2 C8 C20 C21 C24 C27 = CMP-0007318-5: CAP, CERM, 10 uF, 10 V, +/- 20%, X5R, 0603; Manufacturer: MuRata; Polarized: N; Value: 10uF; U/M: EA; Cap_F: 10µF; Value1: Unknown; VDC_V: 10V; TaMin_C: -55°C; TaMax_C: 85°C; AEC Category: Q200; SizeArea_mm2: 1.28; SizeAreaWB_mm2: 4.68; SizeX_mm: 1.6; SizeY_mm: 0.8; SizeZ_mm: 1
C3-C6 C14-C18 = CMP-0006629-2: CAP, CERM, 0.1 uF, 10 V, +/- 10%, X7R, 0402; Manufacturer: MuRata; Polarized: N; Value: 0.1uF; U/M: EA; Cap_F: 100nF; Value1: Unknown; VDC_V: 10V; TaMin_C: -55°C; TaMax_C: 125°C; SizeArea_mm2: 0.5; SizeAreaWB_mm2: 3; SizeX_mm: 1; SizeZ_mm: 0.6; AEC Category: Q200
C7 = CMP-0008285-2: CAP, CERM, 10 uF, 10 V, +/- 10%, X5R, 0805; Manufacturer: MuRata; Polarized: N; Value: 10uF; U/M: EA; Cap_F: 10µF; ESR_ohm: 2m; Value1: 0.002 ohm; VDC_V: 10V; TaMin_C: -55°C; TaMax_C: 85°C; Cap_Case: 0805; AEC Category: Q200; SizeArea_mm2: 2.5; SizeAreaWB_mm2: 6.75; SizeX_mm: 2; SizeY_mm: 1.25; SizeZ_mm: 1.45
C9 C25 C31 = CMP-0006629-2: CAP, CERM, 0.1 uF, 10 V, +/- 10%, X7R, 0402; Manufacturer: MuRata; Polarized: N; Value: 0.1uF; U/M: EA; Cap_F: 100nF; Value1: Unknown; VDC_V: 10V; TaMin_C: -55°C; TaMax_C: 125°C; AEC Category: Q200; SizeArea_mm2: 0.5; SizeAreaWB_mm2: 3; SizeX_mm: 1; SizeZ_mm: 0.6
C10-C13 C19 = CMP-0007323-5: CAP, CERM, 2.2 uF, 10 V, +/- 10%, X5R, 0603; Manufacturer: MuRata; Polarized: N; Value: 2.2uF; U/M: EA; Cap_F: 2.2µF; Value1: Unknown; VDC_V: 10V; TaMin_C: -55°C; TaMax_C: 85°C; AEC Category: Q200; SizeArea_mm2: 1.28; SizeAreaWB_mm2: 4.68; SizeX_mm: 1.6; SizeY_mm: 0.8; SizeZ_mm: 1
C22 C23 = CMP-0006420-2: CAP, CERM, 15 pF, 50 V, +/- 5%, C0G/NP0, 0402; Manufacturer: MuRata; Polarized: N; Value: 15pF; U/M: EA; Value1: Unknown; VDC_V: 50V; TaMin_C: -55°C; TaMax_C: 125°C; AEC Category: Q200; SizeArea_mm2: 0.5; SizeAreaWB_mm2: 3; SizeX_mm: 1; SizeZ_mm: 0.6
C26 C29 C30 = CMP-0006639-2: CAP, CERM, 0.01 uF, 16 V, +/- 10%, X7R, 0402; Manufacturer: MuRata; Polarized: N; Value: 0.01uF; U/M: EA; Cap_F: 10nF; Value1: Unknown; VDC_V: 16V; TaMin_C: -55°C; TaMax_C: 125°C; AEC Category: Q200; SizeArea_mm2: 0.5; SizeAreaWB_mm2: 3; SizeX_mm: 1; SizeZ_mm: 0.6
C28 = CMP-0006638-2: CAP, CERM, 1000 pF, 16 V, +/- 10%, X7R, 0402; Manufacturer: MuRata; Polarized: N; Value: 1000pF; U/M: EA; Cap_F: 1nF; Value1: Unknown; VDC_V: 16V; TaMin_C: -55°C; TaMax_C: 125°C; SizeArea_mm2: 0.5; SizeAreaWB_mm2: 3; SizeX_mm: 1; SizeZ_mm: 0.6; AEC Category: Q200
D1 = CMP-0002960-2: LED, Bright Green, SMD; Manufacturer: Wurth Elektronik; Type: AlInGaP; Vf_V: 2V; Io_A: 20mA; Vr_V: 5V; Tjmax_C: 85°C; Power_TotalModule: 72mW; Value1: 0.072W; Angle: 140; U/M: EA
D2 D3 = CMP-0002951-2: LED, Red, SMD; Manufacturer: Wurth Elektronik; Type: AlInGaP; Vf_V: 1.9V; Io_A: 30mA; Vr_V: 5V; Ir_A: 25µA; Tjmax_C: 85°C; Power_TotalModule: 72mW; Value1: 0.072W; Angle: 140; U/M: EA
L1 = CMP-0003363-1: Ferrite Bead, 220 ohm @ 100 MHz, 2 A, 0805; Manufacturer: MuRata; Imax_A: 2A; DCR_ohm: 0.045; Value1: 0.045 ohm; ZTyp@100MHz_Ohm: 220; SizeArea_mm2: 2.5; SizeAreaWB_mm2: 6.75; SizeX_mm: 2; SizeY_mm: 1.25; SizeZ_mm: 1.45
L2 = CMP-0003306-1: Ferrite Bead, 60 ohm @ 100 MHz, 3 A, 0805; Manufacturer: Taiyo Yuden; Imax_A: 3A; DCR_ohm: 0.025; Value1: 0.025 ohm; ZTyp@100MHz_Ohm: 60; SizeArea_mm2: 2.5; SizeAreaWB_mm2: 6.75; SizeX_mm: 2; SizeY_mm: 1.25; SizeZ_mm: 1.45
L3 = CMP-0058752-1: Inductor, Multilayer, Ferrite, 2.2 uH, 1.3 A, 0.08 ohm, SMD; Manufacturer: MuRata; Value: 2.2uH; Ind_H: 2.2µH; Imax_A: 1.3A; Irms: 1.3A @ 40C rise; DCR_ohm: 0.08; AEC Category: Q200; SizeAreaWB_mm2: 10.5; SizeArea_mm2: 5; SizeX_mm: 2.5; SizeY_mm: 2; SizeZ_mm: 1.2; Green_Lifecycle: Active; Green_REACh: Passed
R10 R11 R23 = CMP-0026962-3: RES, 680, 5%, 0.063 W, AEC-Q200 Grade 0, 0402; Manufacturer: Vishay-Dale; Value: 680; Value_Code: 680R; Power_W: 63mW; Value2: 0.063W; VDC_V: 50V; TempCo: 200 ppm/C; EIA_Code: E24; AEC Category: Q200; AEC Qualified: Y; AEC Grade: 0; SizeArea_mm2: 0.5; SizeX_mm: 1; SizeZ_mm: 0.6
R12 R13 = CMP-0026826-2: RES, 10 M, 5%, 0.063 W, AEC-Q200 Grade 0, 0402; Manufacturer: Vishay-Dale; Value: 10Meg; Value_Code: 10M0; Power_W: 63mW; Value2: 0.063W; VDC_V: 50V; TempCo: 200 ppm/C; SizeArea_mm2: 0.5; SizeX_mm: 1; SizeZ_mm: 0.6; EIA_Code: E24; AEC Category: Q200; AEC Qualified: Y; AEC Grade: 0
R14 R15 R20 = CMP-0020442-3: RES, 0, 5%, 0.125 W, AEC-Q200 Grade 0, 0805; Manufacturer: Vishay-Dale; Value: 0; Value_Code: 0000; Power_W: 125mW; Value2: 0.125W; VDC_V: 150V; TempCo: 200 ppm/C; EIA_Code: E24; AEC Category: Q200; AEC Qualified: Y; SizeArea_mm2: 2.5; SizeX_mm: 2; SizeY_mm: 1.25; SizeZ_mm: 1.45
R16-R19 R21 R22 R28 R32 = CMP-0025697-4: as R3 on sheet MCU009B_Connector+IO
R24 = CMP-0026129-2: RES, 1.00, 1%, 0.063 W, AEC-Q200 Grade 0, 0402; Manufacturer: Vishay-Dale; Value: 1.00; Res_ohm: 1; Value_Code: 1R00; Power_W: 63mW; Value2: 0.063W; VDC_V: 50V; TempCo: 100 ppm/C; SizeArea_mm2: 0.5; SizeZ_mm: 0.6; EIA_Code: E96; AEC Category: Q200; AEC Qualified: Y; AEC Grade: 0
R25 R26 = CMP-0026949-3: RES, 56 k, 5%, 0.063 W, AEC-Q200 Grade 0, 0402; Manufacturer: Vishay-Dale; Value: 56k; Value_Code: 56k0; Power_W: 63mW; Value2: 0.063W; VDC_V: 50V; TempCo: 200 ppm/C; EIA_Code: E24; AEC Category: Q200; AEC Qualified: Y; AEC Grade: 0; SizeArea_mm2: 0.5; SizeX_mm: 1; SizeZ_mm: 0.6
R27 R30 R31 R33 R34 = CMP-0026890-5: RES, 2.2 k, 5%, 0.063 W, AEC-Q200 Grade 0, 0402; Manufacturer: Vishay-Dale; Value: 2.2k; Value_Code: 2k20; Power_W: 63mW; Value2: 0.063W; VDC_V: 50V; TempCo: 200 ppm/C; EIA_Code: E24; AEC Category: Q200; AEC Qualified: Y; AEC Grade: 0; SizeArea_mm2: 0.5; SizeX_mm: 1; SizeZ_mm: 0.6
R29 = CMP-0026822-3: RES, 0, 5%, 0.063 W, AEC-Q200 Grade 0, 0402; Manufacturer: Vishay-Dale; Value: 0; Value_Code: 0000; Power_W: 63mW; Value2: 0.063W; VDC_V: 50V; TempCo: 200 ppm/C; SizeArea_mm2: 0.5; SizeX_mm: 1; SizeZ_mm: 0.6; EIA_Code: E24; AEC Category: Q200; AEC Qualified: Y
S1 = CMP-0002230-1: Switch, SPST, 2 Pos, 25mA, 24VDC, SMD; Manufacturer: CTS Electrocomponents; VDC_V: 24V; SwitchFunction: Off-On; PositionCount: 2; CurrentRating_mA: 25A
TP1-TP6 = CMP-0078143-2: TEST POINT.  No entry in BOM.
U1#1 = CMP-0078352-1: as U1#1 on sheet MCU009B_Connector+IO
U2 = CMP-0051789-2: Dual Buffer/Driver with Open-Drain Output, DBV0006A, LARGE T&R; Manufacturer: Texas Instruments; 3-State Output: No; Bits(#): 2; F @ Nom Voltage(Max)(Mhz): 150; ICC @ Nom Voltage(Max)(mA): 0.01; Input Type: CMOS/TTL; Logic: True; Output Drive (IOL/IOH)(Max)(mA): 32/-32; Output Type: CMOS; Rating: Catalog; Sub-Family: Inverting Buffer/Driver; Technology Family: LVC; tpd @ Nom Voltage(Max)(ns): 8.6,4.4,3.7,2.9; VCC(Max)(V): 5.5; VCC(Min)(V): 1.65; Voltage(Nom)(V): 1.8,2.5,3.3,5; AEC Category: Q200; AEC Qualified: N; CompType: IC; Green_Lifecycle: Active; Green_REACh: Passed; SizeArea_mm2: 8.12; SizeAreaWB_mm2: 14.82; SizeX_mm: 2.8; SizeY_mm: 2.9; SizeZ_mm: 1.45
U3 = CMP-0036866-2: Single Output Low Noise LDO, 400 mA, Fixed 3.3 V Output, 1.7 to 5.5 V Input, with Reverse Current Protection, 5-pin SOT-23 (DBV), -40 to 85 degC, Green (RoHS & no Sb/Br); Manufacturer: Texas Instruments; Alternate PartNumber: TPS73633DBVT; Accuracy(%): 1; Fixed Output Options(V): 3.3; Iout(Max)(A): 0.4; Iq(Typ)(mA): 0.3; Rating: Catalog; SubFamily: Single Channel LDO; Vdo(Typ)(mV): 75; Vin(Max)(V): 5.5; Vin(Min)(V): 1.7; AEC Category: Q200; AEC Qualified: N; CompType: IC; Green_Lifecycle: Active; Green_REACh: Passed; SizeArea_mm2: 8.12; SizeAreaWB_mm2: 14.82; SizeX_mm: 2.8; SizeY_mm: 2.9; SizeZ_mm: 1.45
U4 = CMP-0067340-2: High-Accuracy, Fixed-Threshold OV/UV Monitor, DDC0006A (SOT-23-T-6); Alternate PartNumber: TPS3702CX33DDCT; Manufacturer: Texas Instruments; SizeZ_mm: 0.87; SizeX_mm: 1.65; SizeY_mm: 2.95; SizeArea_mm2: 4.8675; CompType: IC; U/M: EA; SizeAreaWB_mm2: 10.4675
Y1 = CMP-0080365-1: Crystal, 20 MHz, 25 ppm, 18, SMD; PartNumber: ECS-200-18-30B-AGN-TR; Manufacturer: ECS Inc.; Frequency Stability: 30 ppm; AEC Qualified: N; Frequency Tolerance: 25 ppm; AEC Category: Q200; TaMax_C: 85°C; TaMin_C: -40°C; Load Capacitance: 18

## Sheet MCU009B_ADC.SchDoc: ADC
size 431 x 279 mm; Date: Not shown in title block; ApprovedBy: Not shown in title block; CheckedBy: Not shown in title block; Author: Not shown in title block; CompanyName: Not shown in title block; Engineer: Not shown in title block; Organization: Not shown in title block; Address1: Not shown in title block; Address2: Not shown in title block; Address3: Not shown in title block; Address4: Not shown in title block; DocumentNumber: 4; Revision: Use project parameter SCH_Rev; SheetNumber: 4; SheetTotal: 7; PageSetup: Record=PageOptions¦CenterHorizontal=True¦CenterVertical=True¦PrintScale=1.00¦XCorrection=1.00¦YCorrection=1.00¦PrintKind=0¦BorderSize=5000000¦LeftOffset=0¦BottomOffset=0¦Orientation=2¦PaperLength=1000¦PaperWidth=1000¦Scale=100¦PaperSource=15¦PrintQuality=600¦MediaType=1¦DitherType=10¦PaperKind=Letter¦PrintScaleMode=1
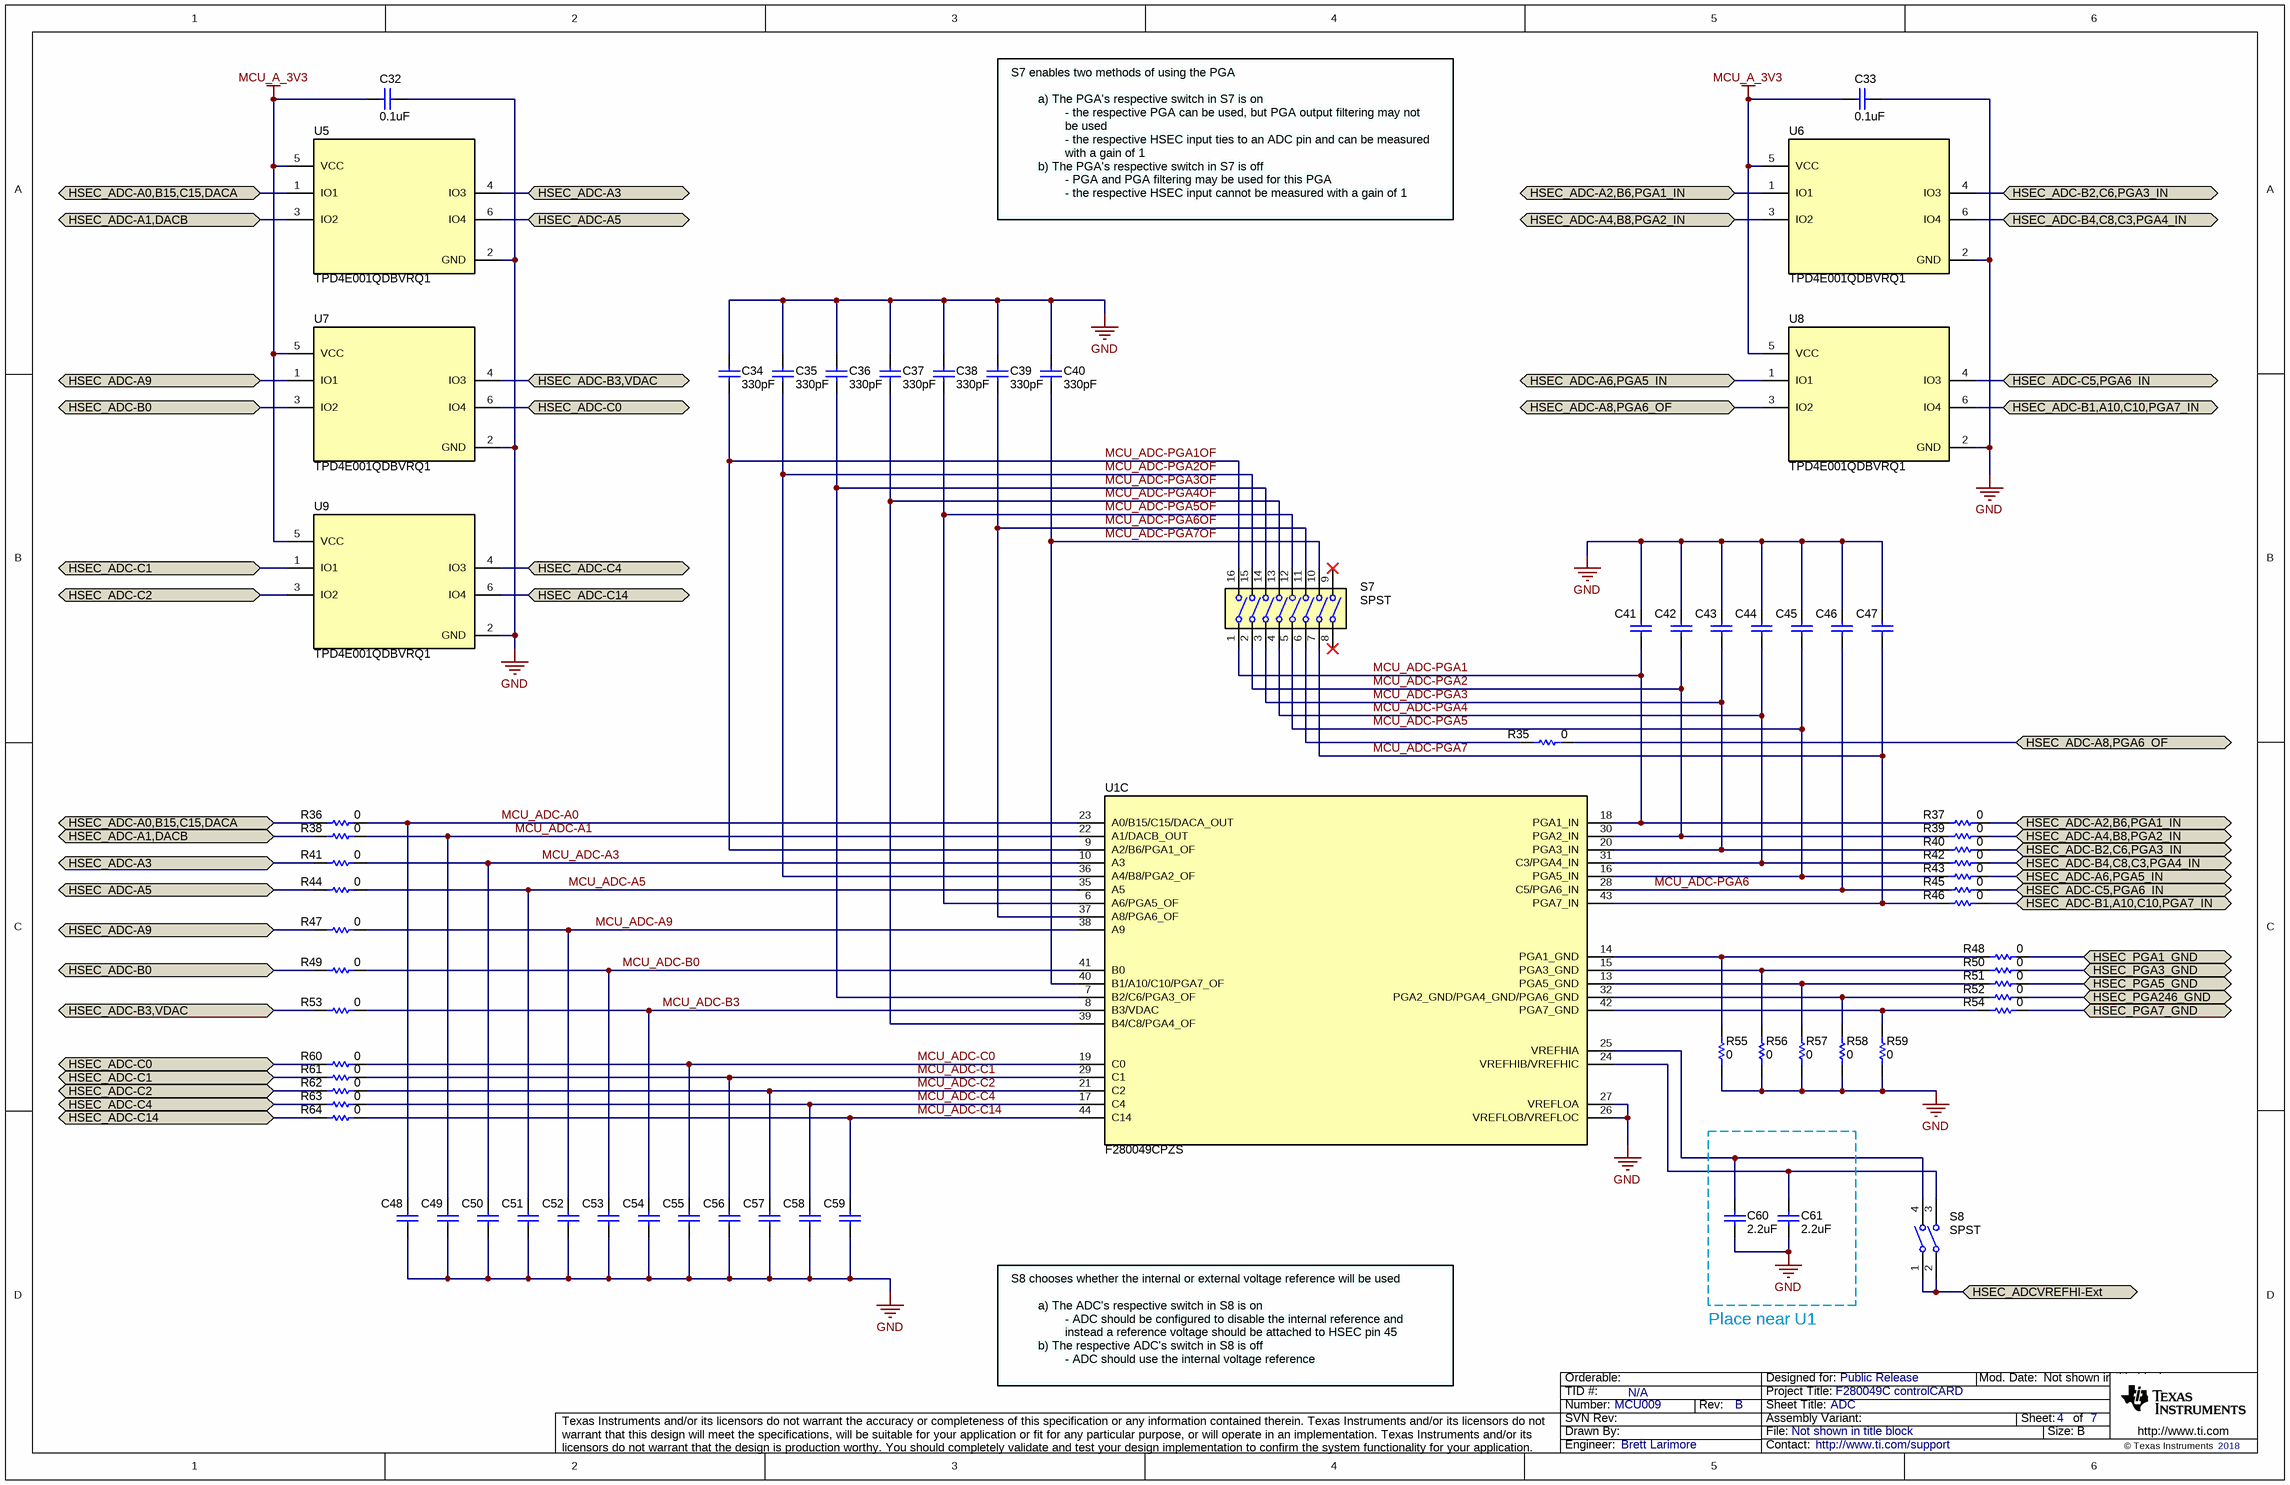
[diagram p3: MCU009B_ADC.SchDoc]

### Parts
(Parts that share a designator on the sheet are numbered #1, #2 ... from top to bottom, then left to right.)
C32  ValueDisplayed: 0.1uF  [0402]  (hidden comment: GRM155R71A104KA01D)
C33  ValueDisplayed: 0.1uF  [0402]  (hidden comment: GRM155R71A104KA01D)
C34  ValueDisplayed: 330pF  [0603]  (hidden comment: GRM1885C1H331JA01D)
C35  ValueDisplayed: 330pF  [0603]  (hidden comment: GRM1885C1H331JA01D)
C36  ValueDisplayed: 330pF  [0603]  (hidden comment: GRM1885C1H331JA01D)
C37  ValueDisplayed: 330pF  [0603]  (hidden comment: GRM1885C1H331JA01D)
C38  ValueDisplayed: 330pF  [0603]  (hidden comment: GRM1885C1H331JA01D)
C39  ValueDisplayed: 330pF  [0603]  (hidden comment: GRM1885C1H331JA01D)
C40  ValueDisplayed: 330pF  [0603]  (hidden comment: GRM1885C1H331JA01D)
C41  GRM188R71C104KA01D  [0603]  (value not drawn)
C42  GRM188R71C104KA01D  [0603]  (value not drawn)
C43  GRM188R71C104KA01D  [0603]  (value not drawn)
C44  GRM188R71C104KA01D  [0603]  (value not drawn)
C45  GRM188R71C104KA01D  [0603]  (value not drawn)
C46  GRM188R71C104KA01D  [0603]  (value not drawn)
C47  GRM188R71C104KA01D  [0603]  (value not drawn)
C48  GRM188R71C104KA01D  [0603]  (value not drawn)
C49  GRM188R71C104KA01D  [0603]  (value not drawn)
C50  GRM188R71C104KA01D  [0603]  (value not drawn)
C51  GRM188R71C104KA01D  [0603]  (value not drawn)
C52  GRM188R71C104KA01D  [0603]  (value not drawn)
C53  GRM188R71C104KA01D  [0603]  (value not drawn)
C54  GRM188R71C104KA01D  [0603]  (value not drawn)
C55  GRM188R71C104KA01D  [0603]  (value not drawn)
C56  GRM188R71C104KA01D  [0603]  (value not drawn)
C57  GRM188R71C104KA01D  [0603]  (value not drawn)
C58  GRM188R71C104KA01D  [0603]  (value not drawn)
C59  GRM188R71C104KA01D  [0603]  (value not drawn)
C60  ValueDisplayed: 2.2uF  [0603]  (hidden comment: GRM188R61A225KE34D)
C61  ValueDisplayed: 2.2uF  [0603]  (hidden comment: GRM188R61A225KE34D)
R35  ValueDisplayed: 0  [0603]  (hidden comment: CRCW06030000Z0EA)
R36  ValueDisplayed: 0  [0603]  (hidden comment: CRCW06030000Z0EA)
R37  ValueDisplayed: 0  [0603]  (hidden comment: CRCW06030000Z0EA)
R38  ValueDisplayed: 0  [0603]  (hidden comment: CRCW06030000Z0EA)
R39  ValueDisplayed: 0  [0603]  (hidden comment: CRCW06030000Z0EA)
R40  ValueDisplayed: 0  [0603]  (hidden comment: CRCW06030000Z0EA)
R41  ValueDisplayed: 0  [0603]  (hidden comment: CRCW06030000Z0EA)
R42  ValueDisplayed: 0  [0603]  (hidden comment: CRCW06030000Z0EA)
R43  ValueDisplayed: 0  [0603]  (hidden comment: CRCW06030000Z0EA)
R44  ValueDisplayed: 0  [0603]  (hidden comment: CRCW06030000Z0EA)
R45  ValueDisplayed: 0  [0603]  (hidden comment: CRCW06030000Z0EA)
R46  ValueDisplayed: 0  [0603]  (hidden comment: CRCW06030000Z0EA)
R47  ValueDisplayed: 0  [0603]  (hidden comment: CRCW06030000Z0EA)
R48  ValueDisplayed: 0  [0603]  (hidden comment: CRCW06030000Z0EA)
R49  ValueDisplayed: 0  [0603]  (hidden comment: CRCW06030000Z0EA)
R50  ValueDisplayed: 0  [0603]  (hidden comment: CRCW06030000Z0EA)
R51  ValueDisplayed: 0  [0603]  (hidden comment: CRCW06030000Z0EA)
R52  ValueDisplayed: 0  [0603]  (hidden comment: CRCW06030000Z0EA)
R53  ValueDisplayed: 0  [0603]  (hidden comment: CRCW06030000Z0EA)
R54  ValueDisplayed: 0  [0603]  (hidden comment: CRCW06030000Z0EA)
R55  ValueDisplayed: 0  [0603]  (hidden comment: CRCW06030000Z0EA)
R56  ValueDisplayed: 0  [0603]  (hidden comment: CRCW06030000Z0EA)
R57  ValueDisplayed: 0  [0603]  (hidden comment: CRCW06030000Z0EA)
R58  ValueDisplayed: 0  [0603]  (hidden comment: CRCW06030000Z0EA)
R59  ValueDisplayed: 0  [0603]  (hidden comment: CRCW06030000Z0EA)
R60  ValueDisplayed: 0  [0603]  (hidden comment: CRCW06030000Z0EA)
R61  ValueDisplayed: 0  [0603]  (hidden comment: CRCW06030000Z0EA)
R62  ValueDisplayed: 0  [0603]  (hidden comment: CRCW06030000Z0EA)
R63  ValueDisplayed: 0  [0603]  (hidden comment: CRCW06030000Z0EA)
R64  ValueDisplayed: 0  [0603]  (hidden comment: CRCW06030000Z0EA)
S7  Circuit: SPST  [SW_218-8LP]  (hidden comment: 218-8LPST)
S8  Circuit: SPST  [SW_218-2LP]  (hidden comment: 218-2LPST)
U1#2  F280049CPZS  [PZ0100A_N]  (part C of 5)
U5  TPD4E001QDBVRQ1  [DBV0006A_N]
U6  TPD4E001QDBVRQ1  [DBV0006A_N]
U7  TPD4E001QDBVRQ1  [DBV0006A_N]
U8  TPD4E001QDBVRQ1  [DBV0006A_N]
U9  TPD4E001QDBVRQ1  [DBV0006A_N]

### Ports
HSEC_ADC-A0,B15,C15,DACA (bidir), HSEC_ADC-A1,DACB (bidir), HSEC_ADC-A2,B6,PGA1_IN (bidir), HSEC_ADC-A3 (bidir), HSEC_ADC-A4,B8,PGA2_IN (bidir), HSEC_ADC-A5 (bidir), HSEC_ADC-A6,PGA5_IN (bidir), HSEC_ADC-A8,PGA6_OF (bidir), HSEC_ADC-A9 (bidir), HSEC_ADC-B0 (bidir), HSEC_ADC-B1,A10,C10,PGA7_IN (bidir), HSEC_ADC-B2,C6,PGA3_IN (bidir), HSEC_ADC-B3,VDAC (bidir), HSEC_ADC-B4,C8,C3,PGA4_IN (bidir), HSEC_ADC-C0 (bidir), HSEC_ADC-C1 (bidir), HSEC_ADC-C2 (bidir), HSEC_ADC-C4 (bidir), HSEC_ADC-C5,PGA6_IN (bidir), HSEC_ADC-C14 (bidir), HSEC_ADCVREFHI-Ext (bidir), HSEC_PGA1_GND (bidir), HSEC_PGA3_GND (bidir), HSEC_PGA5_GND (bidir), HSEC_PGA7_GND (bidir), HSEC_PGA246_GND (bidir)

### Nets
GND: C32.2 C33.2 C34.1 C35.1 C36.1 C37.1 C38.1 C39.1 C40.1 C41.1 C42.1 C43.1 C44.1 C45.1 C46.1 C47.1 C48.2 C49.2 C50.2 C51.2 C52.2 C53.2 C54.2 C55.2 C56.2 C57.2 C58.2 C59.2 C60.1 C61.1 R55.1 R56.1 R57.1 R58.1 R59.1 U1#2.26(VREFLOB/VREFLOC) U1#2.27(VREFLOA) U5.2(GND) U6.2(GND) U7.2(GND) U8.2(GND) U9.2(GND)
MCU_A_3V3: C32.1 C33.1 U5.5(VCC) U6.5(VCC) U7.5(VCC) U8.5(VCC) U9.5(VCC)
HSEC_ADC-A0,B15,C15,DACA: R36.2 U5.1(IO1) ; port HSEC_ADC-A0,B15,C15,DACA
HSEC_ADC-A1,DACB: R38.2 U5.3(IO2) ; port HSEC_ADC-A1,DACB
HSEC_ADC-A2,B6,PGA1_IN: R37.1 U6.1(IO1) ; port HSEC_ADC-A2,B6,PGA1_IN
HSEC_ADC-A3: R41.2 U5.4(IO3) ; port HSEC_ADC-A3
HSEC_ADC-A4,B8,PGA2_IN: R39.1 U6.3(IO2) ; port HSEC_ADC-A4,B8,PGA2_IN
HSEC_ADC-A5: R44.2 U5.6(IO4) ; port HSEC_ADC-A5
HSEC_ADC-A6,PGA5_IN: R43.1 U8.1(IO1) ; port HSEC_ADC-A6,PGA5_IN
HSEC_ADC-A8,PGA6_OF: R35.1 U8.3(IO2) ; port HSEC_ADC-A8,PGA6_OF
HSEC_ADC-A9: R47.2 U7.1(IO1) ; port HSEC_ADC-A9
HSEC_ADC-B0: R49.2 U7.3(IO2) ; port HSEC_ADC-B0
HSEC_ADC-B1,A10,C10,PGA7_IN: R46.1 U8.6(IO4) ; port HSEC_ADC-B1,A10,C10,PGA7_IN
HSEC_ADC-B2,C6,PGA3_IN: R40.1 U6.4(IO3) ; port HSEC_ADC-B2,C6,PGA3_IN
HSEC_ADC-B3,VDAC: R53.2 U7.4(IO3) ; port HSEC_ADC-B3,VDAC
HSEC_ADC-B4,C8,C3,PGA4_IN: R42.1 U6.6(IO4) ; port HSEC_ADC-B4,C8,C3,PGA4_IN
HSEC_ADC-C0: R60.2 U7.6(IO4) ; port HSEC_ADC-C0
HSEC_ADC-C1: R61.2 U9.1(IO1) ; port HSEC_ADC-C1
HSEC_ADC-C2: R62.2 U9.3(IO2) ; port HSEC_ADC-C2
HSEC_ADC-C4: R63.2 U9.4(IO3) ; port HSEC_ADC-C4
HSEC_ADC-C5,PGA6_IN: R45.1 U8.4(IO3) ; port HSEC_ADC-C5,PGA6_IN
HSEC_ADC-C14: R64.2 U9.6(IO4) ; port HSEC_ADC-C14
HSEC_ADCVREFHI-Ext: S8.1 S8.2 ; port HSEC_ADCVREFHI-Ext
HSEC_PGA1_GND: R48.1 ; port HSEC_PGA1_GND
HSEC_PGA3_GND: R50.1 ; port HSEC_PGA3_GND
HSEC_PGA5_GND: R51.1 ; port HSEC_PGA5_GND
HSEC_PGA7_GND: R54.1 ; port HSEC_PGA7_GND
HSEC_PGA246_GND: R52.1 ; port HSEC_PGA246_GND
MCU_ADC-A0: C48.1 R36.1 U1#2.23(A0/B15/C15/DACA_OUT)
MCU_ADC-A1: C49.1 R38.1 U1#2.22(A1/DACB_OUT)
MCU_ADC-A3: C50.1 R41.1 U1#2.10(A3)
MCU_ADC-A5: C51.1 R44.1 U1#2.35(A5)
MCU_ADC-A9: C52.1 R47.1 U1#2.38(A9)
MCU_ADC-B0: C53.1 R49.1 U1#2.41(B0)
MCU_ADC-B3: C54.1 R53.1 U1#2.8(B3/VDAC)
MCU_ADC-C0: C55.1 R60.1 U1#2.19(C0)
MCU_ADC-C1: C56.1 R61.1 U1#2.29(C1)
MCU_ADC-C2: C57.1 R62.1 U1#2.21(C2)
MCU_ADC-C4: C58.1 R63.1 U1#2.17(C4)
MCU_ADC-C14: C59.1 R64.1 U1#2.44(C14)
MCU_ADC-PGA1: C41.2 R37.2 S7.1 U1#2.18(PGA1_IN)
MCU_ADC-PGA1OF: C34.2 S7.16(1A) U1#2.9(A2/B6/PGA1_OF)
MCU_ADC-PGA2: C42.2 R39.2 S7.2 U1#2.30(PGA2_IN)
MCU_ADC-PGA2OF: C35.2 S7.15(2A) U1#2.36(A4/B8/PGA2_OF)
MCU_ADC-PGA3: C43.2 R40.2 S7.3 U1#2.20(PGA3_IN)
MCU_ADC-PGA3OF: C36.2 S7.14(3A) U1#2.7(B2/C6/PGA3_OF)
MCU_ADC-PGA4: C44.2 R42.2 S7.4 U1#2.31(C3/PGA4_IN)
MCU_ADC-PGA4OF: C37.2 S7.13(4A) U1#2.39(B4/C8/PGA4_OF)
MCU_ADC-PGA5: C45.2 R43.2 S7.5 U1#2.16(PGA5_IN)
MCU_ADC-PGA5OF: C38.2 S7.12(5A) U1#2.6(A6/PGA5_OF)
MCU_ADC-PGA6: C46.2 R45.2 U1#2.28(C5/PGA6_IN)
MCU_ADC-PGA6OF: C39.2 S7.11(6A) U1#2.37(A8/PGA6_OF)
MCU_ADC-PGA7: C47.2 R46.2 S7.7 U1#2.43(PGA7_IN)
MCU_ADC-PGA7OF: C40.2 S7.10(7A) U1#2.40(B1/A10/C10/PGA7_OF)
NetC60_2: C60.2 S8.4 U1#2.25(VREFHIA)
NetC61_2: C61.2 S8.3 U1#2.24(VREFHIB/VREFHIC)
NetR35_2: R35.2 S7.6
NetR48_2: R48.2 R55.2 U1#2.14(PGA1_GND)
NetR50_2: R50.2 R56.2 U1#2.15(PGA3_GND)
NetR51_2: R51.2 R57.2 U1#2.13(PGA5_GND)
NetR52_2: R52.2 R58.2 U1#2.32(PGA2_GND/PGA4_GND/PGA6_GND)
NetR54_2: R54.2 R59.2 U1#2.42(PGA7_GND)

Not connected (* = marked no-connect by the designer): S7 8* 9(8A)*

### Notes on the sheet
- S7 enables two methods of using the PGA
- a) The PGA's respective switch in S7 is on
- b) The PGA's respective switch in S7 is off
- - the respective HSEC input ties to an ADC pin and can be measured
- - the respective PGA can be used, but PGA output filtering may not
- with a gain of 1
- be used
- - PGA and PGA filtering may be used for this PGA
- - the respective HSEC input cannot be measured with a gain of 1
- S8 chooses whether the internal or external voltage reference will be used
- a) The ADC's respective switch in S8 is on
- b) The respective ADC's switch in S8 is off
- - ADC should be configured to disable the internal reference and
- - ADC should use the internal voltage reference
- instead a reference voltage should be attached to HSEC pin 45
- Place near U1

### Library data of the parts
C32 C33 = CMP-0006629-2: as C9 on sheet MCU009B_Power+Misc
C34-C40 = CMP-0007209-4: CAP, CERM, 330 pF, 50 V, +/- 5%, C0G/NP0, 0603; Manufacturer: MuRata; Polarized: N; Value: 330pF; U/M: EA; Value1: Unknown; VDC_V: 50V; TaMin_C: -55°C; TaMax_C: 125°C; SizeArea_mm2: 1.28; SizeAreaWB_mm2: 4.68; SizeX_mm: 1.6; SizeY_mm: 0.8; SizeZ_mm: 1; AEC Category: Q200
C41-C54 C56-C59 = CMP-0007378-5: CAP, CERM, 0.1 uF, 16 V, +/- 10%, X7R, 0603; Manufacturer: MuRata; Polarized: N; Value: 0.1uF; U/M: EA; Cap_F: 100nF; Value1: Unknown; VDC_V: 16V; TaMin_C: -55°C; TaMax_C: 125°C; SizeArea_mm2: 1.28; SizeAreaWB_mm2: 4.68; SizeX_mm: 1.6; SizeY_mm: 0.8; SizeZ_mm: 1; AEC Category: Q200
C55 = CMP-0007378-5: CAP, CERM, 0.1 uF, 16 V, +/- 10%, X7R, 0603; Manufacturer: MuRata; Polarized: N; CompType: Capacitor; Value: 0.1uF; U/M: EA; Cap_F: 100nF; Value1: Unknown; VDC_V: 16V; TaMin_C: -55°C; TaMax_C: 125°C; SizeArea_mm2: 1.28; SizeAreaWB_mm2: 4.68; SizeX_mm: 1.6; SizeY_mm: 0.8; SizeZ_mm: 1; AEC Category: Q200
C60 C61 = CMP-0007323-5: as C10 on sheet MCU009B_Power+Misc
R35-R64 = CMP-0025697-4: as R3 on sheet MCU009B_Connector+IO
S7 = CMP-0002229-1: Switch, SPST, 8 Pos, 25mA, 24VDC, SMD; Manufacturer: CTS Electrocomponents; VDC_V: 24V; SwitchFunction: Off-On; PositionCount: 8; CurrentRating_mA: 25A
S8 = CMP-0002230-1: as S1 on sheet MCU009B_Power+Misc
U1#2 = CMP-0078352-1: as U1#1 on sheet MCU009B_Connector+IO
U5-U9 = CMP-0066599-1: Automotive Low-Capacitance 4-Channel +/-15-kV ESD Protection Array for High-Speed Data Interfaces, DBV0006A (SOT-23-6); Manufacturer: Texas Instruments; CompType: IC; U/M: EA; SizeArea_mm2: 8.12; SizeAreaWB_mm2: 14.82; SizeX_mm: 2.8; SizeY_mm: 2.9; SizeZ_mm: 1.45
